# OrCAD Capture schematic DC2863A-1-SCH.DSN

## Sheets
1 PAGE2: size C
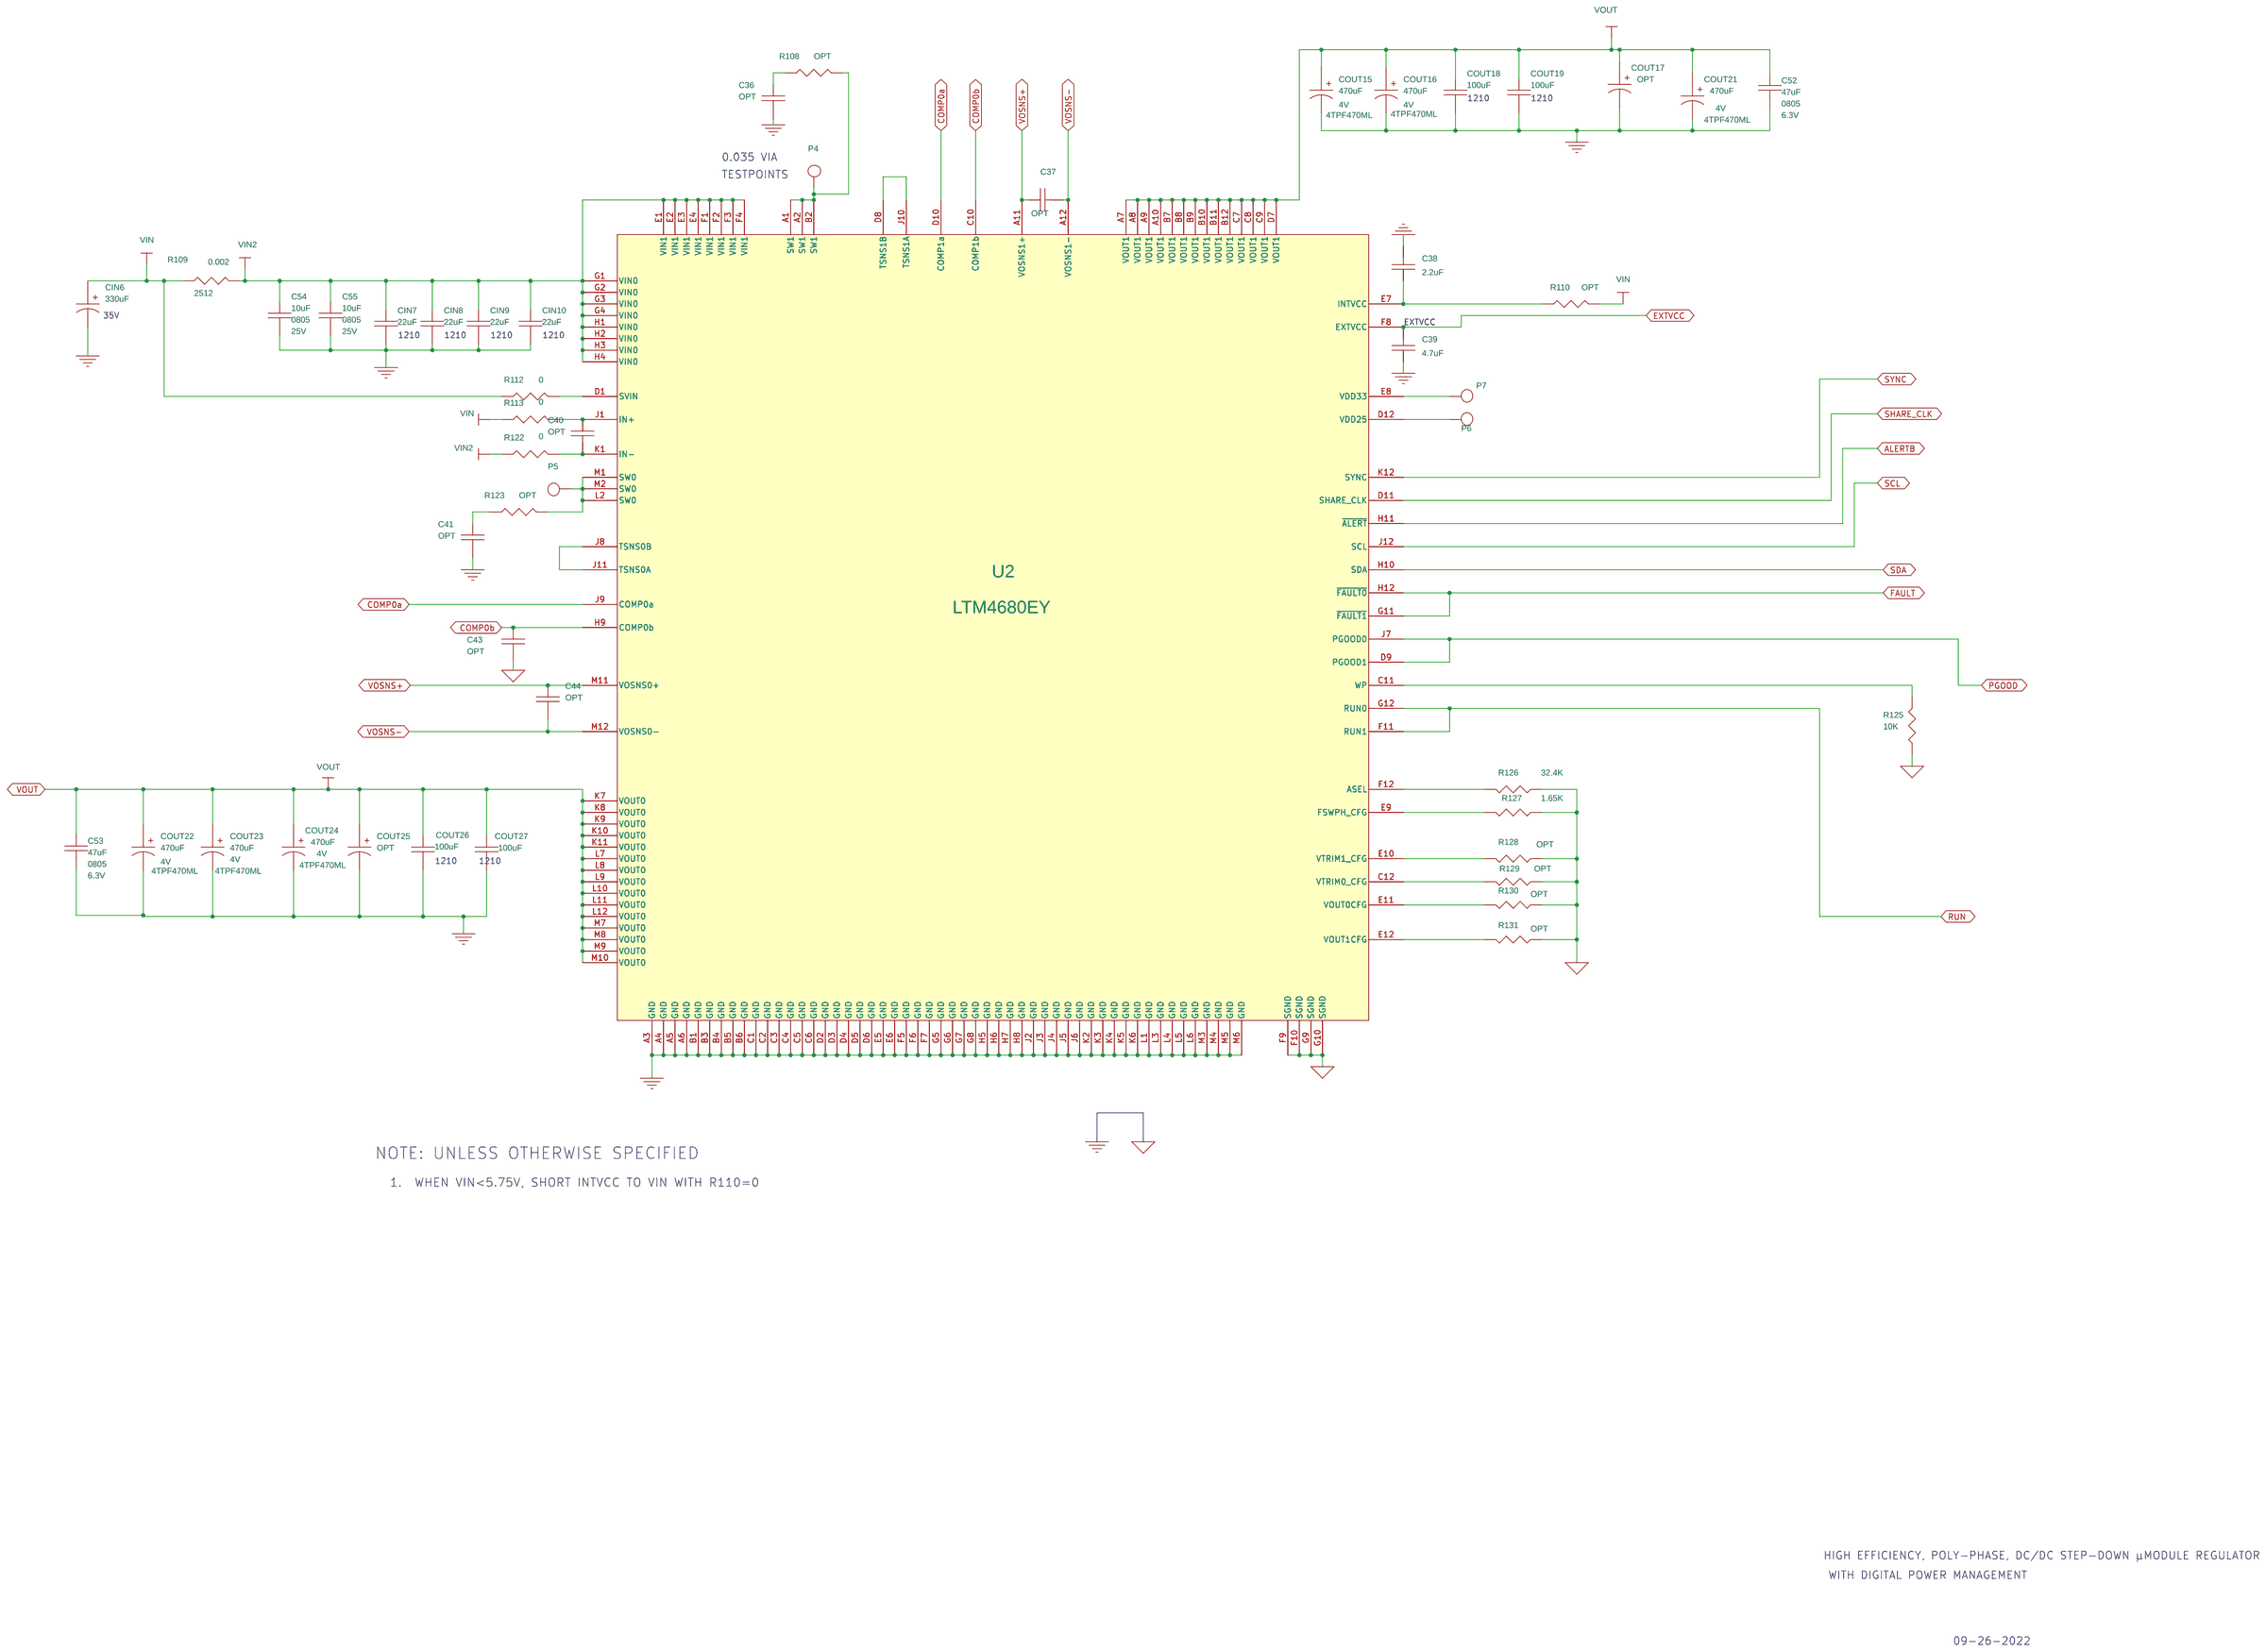
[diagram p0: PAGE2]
2 PAGE4: size B
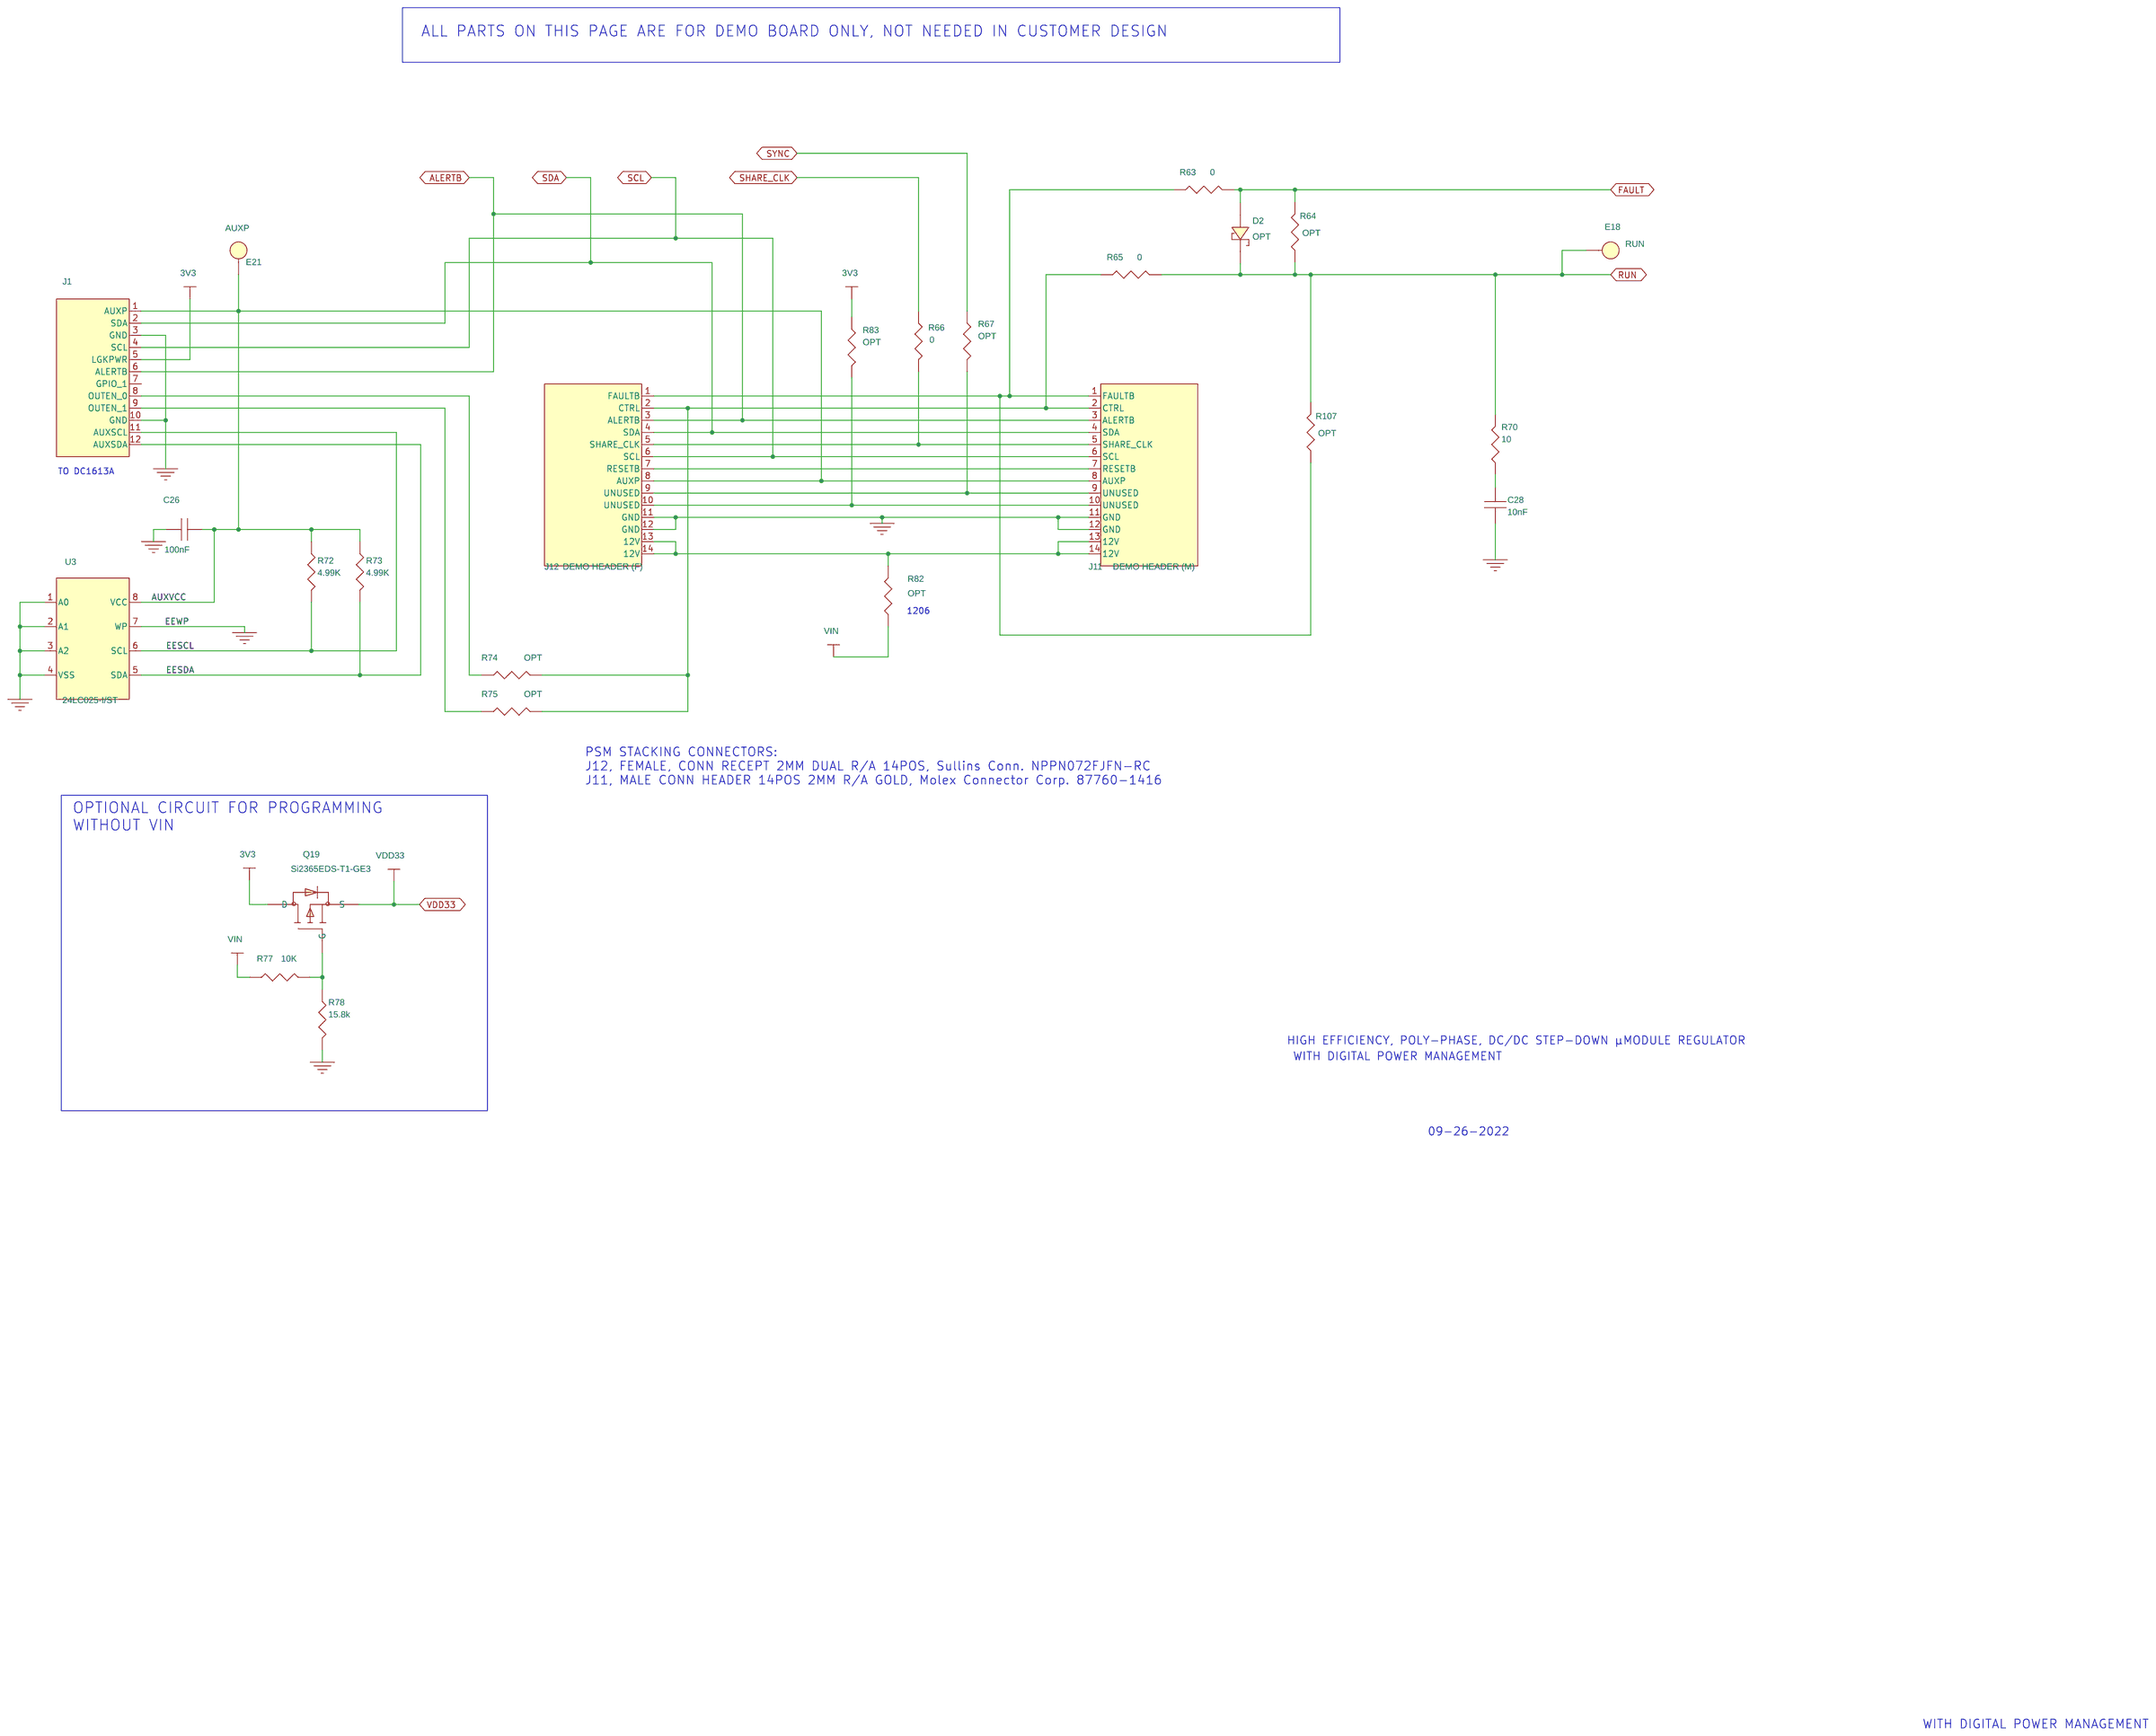
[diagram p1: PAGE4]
3 PAGE1: size C
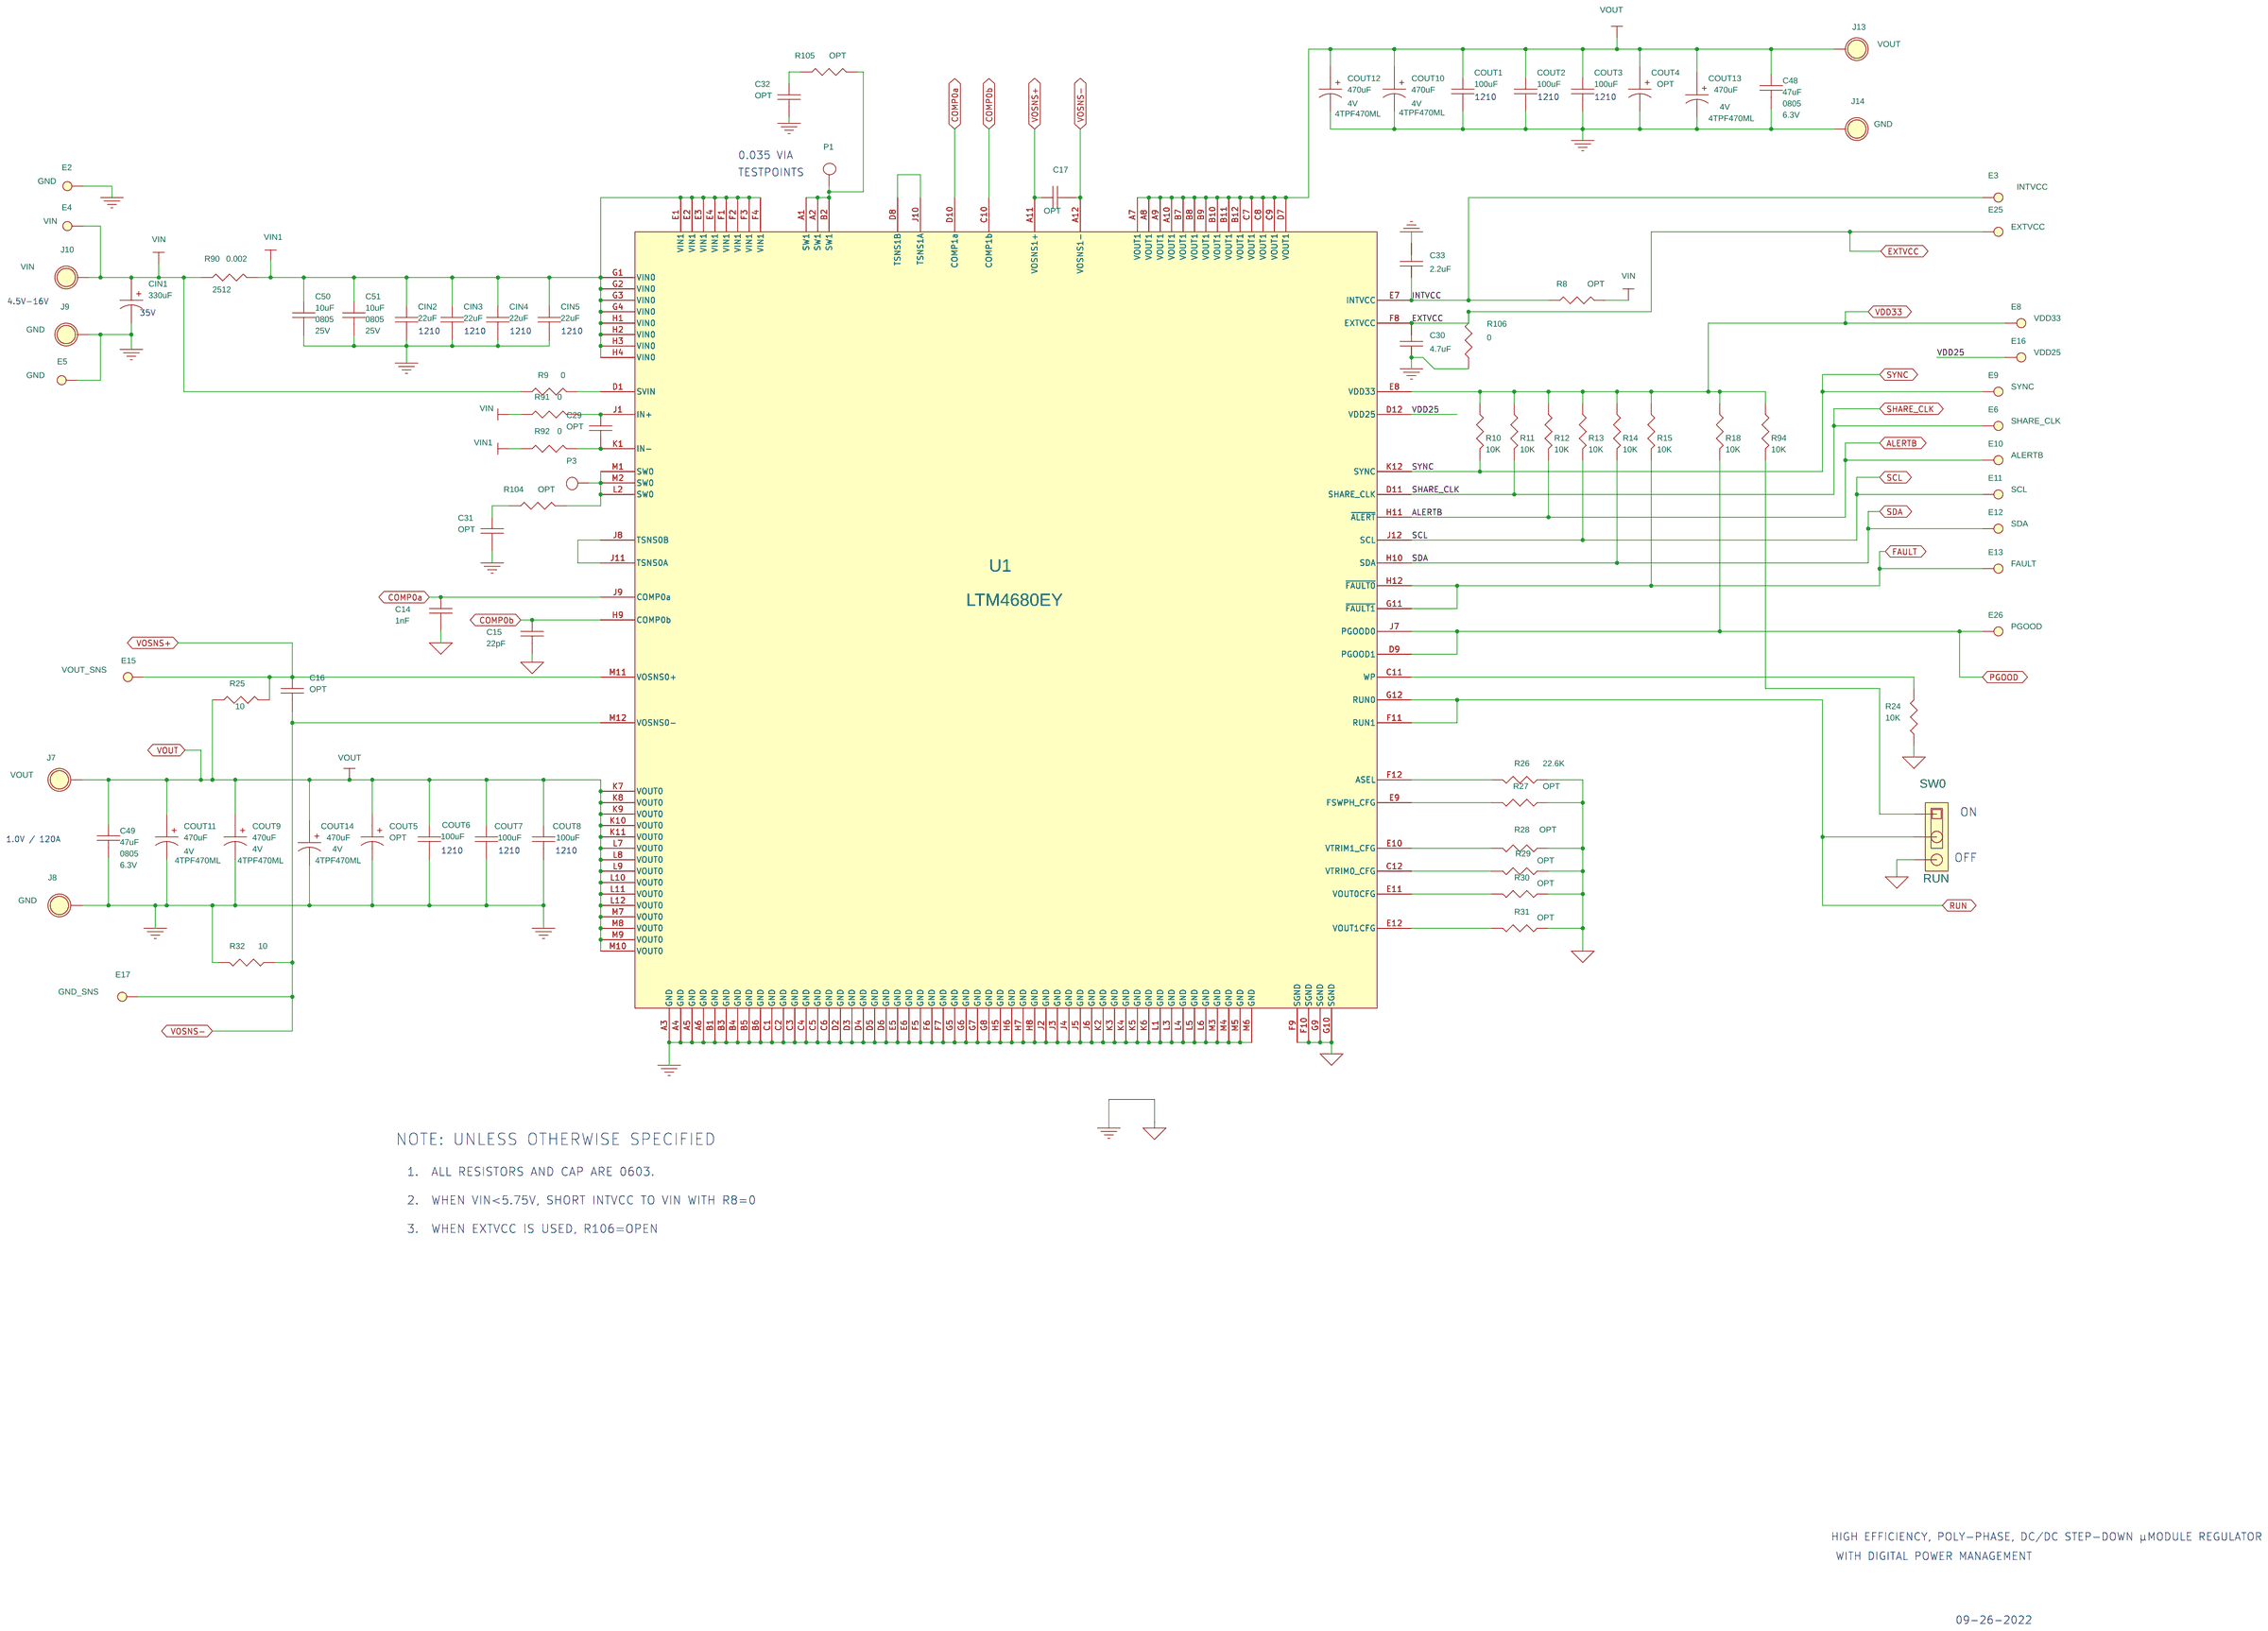
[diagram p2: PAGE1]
4 PAGE3: size Custom
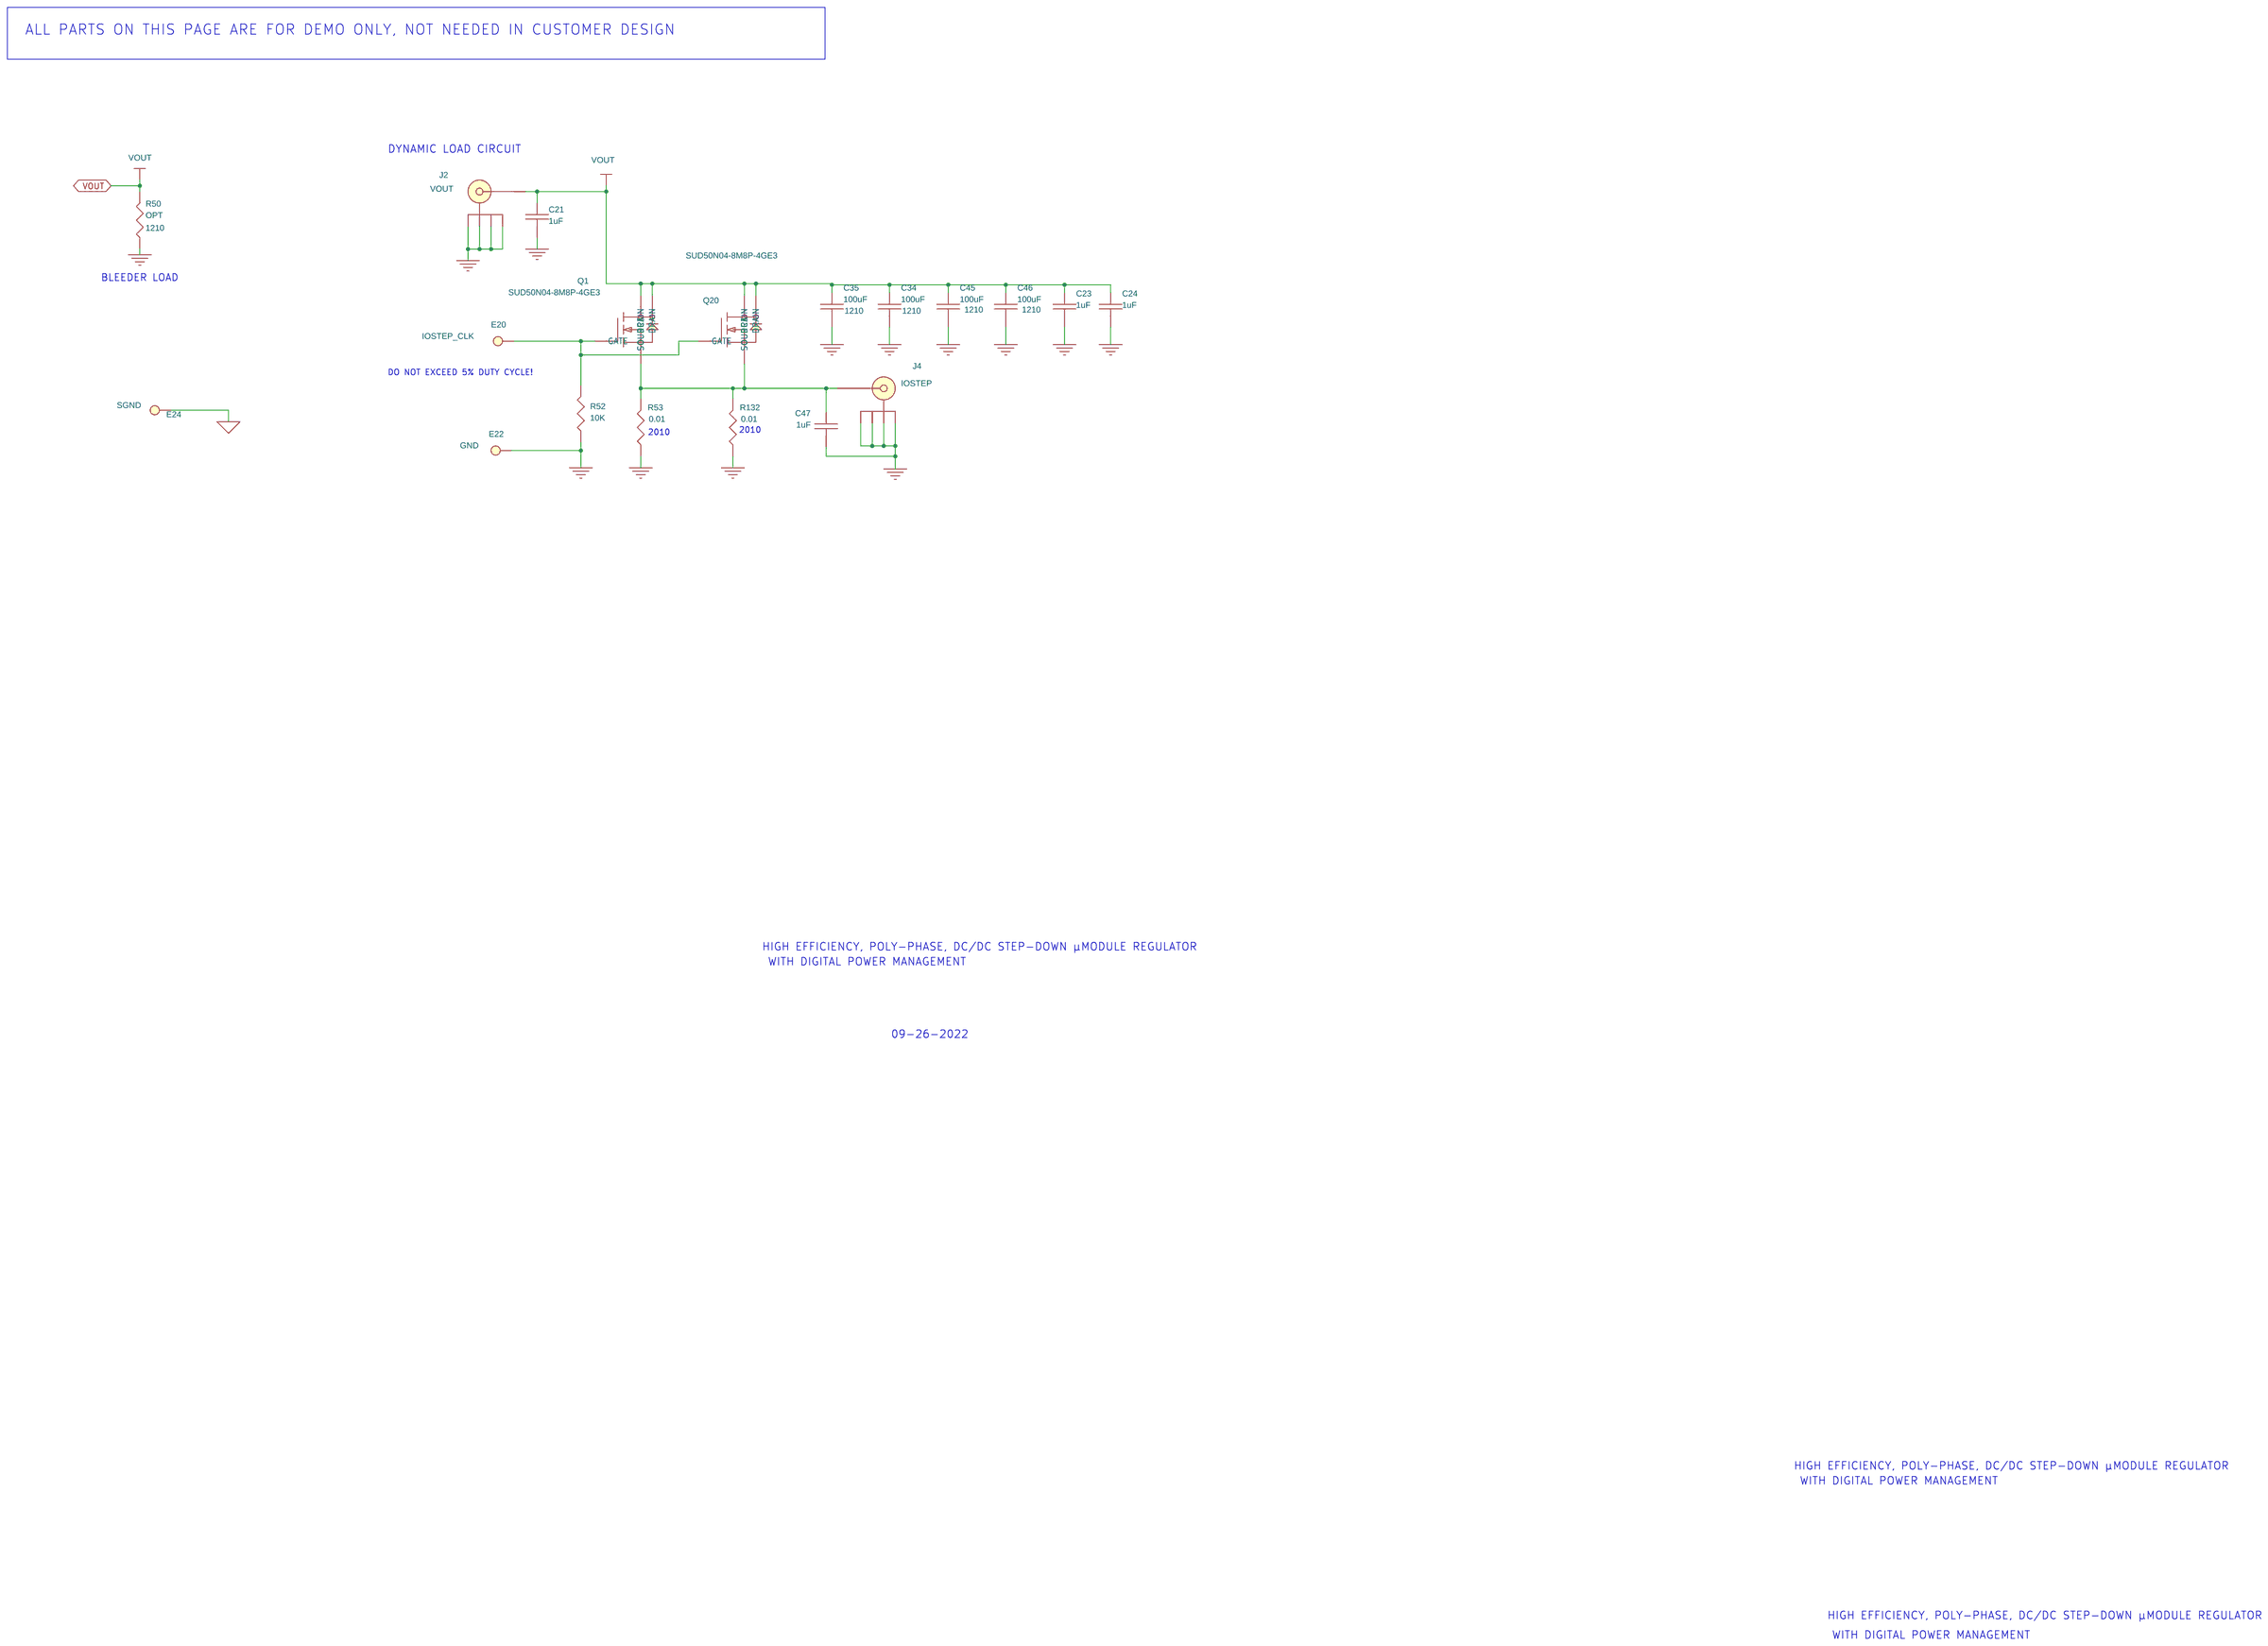
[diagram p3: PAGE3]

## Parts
sheet PAGE1
C14  1nF  [0603]
C15  22pF  [0603]
C16  OPT  [0603]
C17  OPT  [0603]
C29  OPT  [0603]
C30  4.7uF  [0603]
C31  OPT  [0603]
C32  OPT  [0603]
C33  2.2uF  [0603]
C48  47uF  [0805]
C49  47uF  [0805]
C50  10uF  [0805]
C51  10uF  [0805]
CIN1  330uF  [SANYO-F8]
CIN2  22uF  [1210]
CIN3  22uF  [1210]
CIN4  22uF  [1210]
CIN5  22uF  [1210]
COUT1  100uF  [1210]
COUT2  100uF  [1210]
COUT3  100uF  [1210]
COUT4  OPT  [D3L]
COUT5  OPT  [D3L]
COUT6  100uF  [1210]
COUT7  100uF  [1210]
COUT8  100uF  [1210]
COUT9  470uF  [D3L]
COUT10  470uF  [D3L]
COUT11  470uF  [D3L]
COUT12  470uF  [D3L]
COUT13  470uF  [D3L]
COUT14  470uF  [D3L]
E2  GND  [TURRETS]
E3  INTVCC  [TURRETS]
E4  TURRETS  [TURRETS]
E5  GND  [TURRETS]
E6  TURRETS  [TURRETS]
E8  VDD33  [TURRETS]
E9  TURRETS  [TURRETS]
E10  TURRETS  [TURRETS]
E11  TURRETS  [TURRETS]
E12  TURRETS  [TURRETS]
E13  TURRETS  [TURRETS]
E15  TURRETS  [TURRETS]
E16  VDD25  [TURRETS]
E17  TURRETS  [TURRETS]
E25  EXTVCC  [TURRETS]
E26  TURRETS  [TURRETS]
J7  BANANA SMALL  [CON\LUG\10]
J8  BANANA SMALL  [CON\LUG\10]
J9  BANANA SMALL  [CON\LUG\10]
J10  BANANA SMALL  [CON\LUG\10]
J13  BANANA SMALL  [CON\LUG\10]
J14  BANANA SMALL  [CON\LUG\10]
P1  TURRETS  [PAD]
P3  TURRETS  [PAD]
R8  OPT  [0603]
R9  0  [0603]
R10  10K  [0603]
R11  10K  [0603]
R12  10K  [0603]
R13  10K  [0603]
R14  10K  [0603]
R15  10K  [0603]
R18  10K  [0603]
R24  10K  [0603]
R25  10  [0603]
R26  22.6K  [0603]
R27  OPT  [0603]
R28  OPT  [0603]
R29  OPT  [0603]
R30  OPT  [0603]
R31  OPT  [0603]
R32  10  [0603]
R90  0.002  [2512]
R91  0  [0603]
R92  0  [0603]
R94  10K  [0603]
R104  OPT  [0805]
R105  OPT  [0805]
R106  0  [0603]
SW0  3 Pins 2mm Ctrs.  [HD1X3-079]
U1  LTM4680EY  [a]
sheet PAGE2
C36  OPT  [0603]
C37  OPT  [0603]
C38  2.2uF  [0603]
C39  4.7uF  [0603]
C40  OPT  [0603]
C41  OPT  [0603]
C43  OPT  [0603]
C44  OPT  [0603]
C52  47uF  [0805]
C53  47uF  [0805]
C54  10uF  [0805]
C55  10uF  [0805]
CIN6  330uF  [SANYO-F8]
CIN7  22uF  [1210]
CIN8  22uF  [1210]
CIN9  22uF  [1210]
CIN10  22uF  [1210]
COUT15  470uF  [D3L]
COUT16  470uF  [D3L]
COUT17  OPT  [D3L]
COUT18  100uF  [1210]
COUT19  100uF  [1210]
COUT21  470uF  [D3L]
COUT22  470uF  [D3L]
COUT23  470uF  [D3L]
COUT24  470uF  [D3L]
COUT25  OPT  [D3L]
COUT26  100uF  [1210]
COUT27  100uF  [1210]
P4  TURRETS  [PAD]
P5  TURRETS  [PAD]
P6  TURRETS  [PAD]
P7  TURRETS  [PAD]
R108  OPT  [0805]
R109  0.002  [2512]
R110  OPT  [0603]
R112  0  [0603]
R113  0  [0603]
R122  0  [0603]
R123  OPT  [0805]
R125  10K  [0603]
R126  32.4K  [0603]
R127  1.65K  [0603]
R128  OPT  [0603]
R129  OPT  [0603]
R130  OPT  [0603]
R131  OPT  [0603]
U2  LTM4680EY  [a]
sheet PAGE3
C21  1uF  [0603]
C23  1uF  [0805]
C24  1uF  [0603]
C34  100uF  [1210]
C35  100uF  [1210]
C45  100uF  [1210]
C46  100uF  [1210]
C47  1uF  [0603]
E20  IOSTEP_CLK  [TURRETS]
E22  GND  [TURRETS]
E24  SGND  [TURRETS]
J2  VOUT  [BNC]
J4  IOSTEP  [BNC]
Q1  SUD50N04-8M8P-4GE3  [TO252]
Q20  SUD50N04-8M8P-4GE3  [TO252]
R50  OPT  [1210]
R52  10K  [0603]
R53  0.01  [2010]
R132  0.01  [2010]
sheet PAGE4
C26  100nF  [0603]
C28  10nF  [0603]
D2  OPT  [SOD323]
E18  RUN  [TURRETS]
E21  AUXP  [TURRETS]
J1  HD2X6-079  [HD2X6-079-MOLEX]
J11  DEMO HEADER (M)  [NPPN072FJFN]
J12  DEMO HEADER (F)  [NPPN072FJFN-RC]
Q19  Si2365EDS-T1-GE3  [SOT-23]
R63  0  [0603]
R64  OPT  [0603]
R65  0  [0603]
R66  0  [0603]
R67  OPT  [0603]
R70  10  [0603]
R72  4.99K  [0603]
R73  4.99K  [0603]
R74  OPT  [0603]
R75  OPT  [0603]
R77  10K  [0603]
R78  15.8k  [0603]
R82  OPT  [1206]
R83  OPT  [0603]
R107  OPT  [0603]
U3  24LC025-I/ST  [TSSOP-8_4.4MM]

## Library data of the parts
C14-C17 C29-C33 C36-C41 C43 C44 = CAP0603_1: Component: cap; Manufacturer: TDK; Manufacturer P/N: C1608C0G1H102J; Tolerance: 5%; Type: cer 0603; Vendor: Digikey; Vendor P/N: 445-1293-1-ND; Volts/Amps/Watts: 50V
C48 C49 C52 C53 = CAP0603_1: Component: cap; Manufacturer: TDK; Manufacturer P/N: C1608C0G1H102J; Tolerance: 5%; Type: cer 0603; Vendor: Digikey; Vendor P/N: 445-1293-1-ND; Volts/Amps/Watts: 6.3V
C50 C51 C54 C55 = CAP0603_1: Component: cap; Manufacturer: TDK; Manufacturer P/N: C1608C0G1H102J; Tolerance: 5%; Type: cer 0603; Vendor: Digikey; Vendor P/N: 445-1293-1-ND; Volts/Amps/Watts: 25V
CIN1 CIN6 = CAPR12X5_0: Component: cap; Manufacturer: SANYO; Tolerance: 20%; Type: OS-CON; Volts/Amps/Watts: 16V
CIN2-CIN5 CIN7-CIN10 = CAP1210_1: Component: cap; Manufacturer: Taiyo Yuden; Manufacturer P/N: GMK325BJ106KN-T; Tolerance: 10%; Type: cer 1210; Vendor: Digikey; Vendor P/N: 587-1439-1-ND; Volts/Amps/Watts: 35V
C34 C35 C45 C46 COUT1 COUT18 = CAP0603_1: Component: cap; Manufacturer: TDK; Manufacturer P/N: C3225X5R0J107M; Tolerance: 20%; Type: cer 1210 X5R; Vendor: Digikey; Vendor P/N: 445-1437-1-ND; Volts/Amps/Watts: 6.3v
COUT2 COUT3 COUT6-COUT8 COUT19 COUT26 COUT27 = CAP0603_1: Component: cap; Manufacturer: TDK; Manufacturer P/N: C3225X5R0J107M; Part Type: CAP1210; Tolerance: 20%; Type: cer 1210 X5R; Vendor: Digikey; Vendor P/N: 445-1437-1-ND; Volts/Amps/Watts: 6.3v
COUT4 COUT5 COUT17 COUT25 = CAPR12X5_0: Component: cap; Manufacturer: SANYO; Manufacturer P/N: EEFGX0E471R; Tolerance: 20%; Type: SP-CAP; Volts/Amps/Watts: 2.5V
COUT9-COUT16 COUT21-COUT24 = CAPR12X5_0: Component: cap; Manufacturer: SANYO; Manufacturer P/N: 4TPF470ML; Tolerance: 20%; Type: SP-CAP; Volts/Amps/Watts: 4V
E2 E5 E22 = TURRETS_1: Component: tp; Manufacturer: Keystone; Manufacturer P/N: 1593-2; Vendor: Digikey; Vendor P/N: 1593-2K-ND
E3 E8 E16 E20 E24 E25 = TURRETS_1: Component: tp; Label: GND; Manufacturer: Keystone; Manufacturer P/N: 1593-2; Vendor: Digikey; Vendor P/N: 1593-2K-ND
E4 = TURRETS_1: Component: tp; Label: VIN; Manufacturer: Keystone; Manufacturer P/N: 1593-2; Vendor: Digikey; Vendor P/N: 1593-2K-ND
E6 = TURRETS_1: Component: tp; Label: SHARE_CLK; Manufacturer: Keystone; Manufacturer P/N: 1593-2; Vendor: Digikey; Vendor P/N: 1593-2K-ND
E9 = TURRETS_1: Component: tp; Label: SYNC; Manufacturer: Keystone; Manufacturer P/N: 1593-2; Vendor: Digikey; Vendor P/N: 1593-2K-ND
E10 = TURRETS_1: Component: tp; Label: ALERTB; Manufacturer: Keystone; Manufacturer P/N: 1593-2; Vendor: Digikey; Vendor P/N: 1593-2K-ND
E11 = TURRETS_1: Component: tp; Label: SCL; Manufacturer: Keystone; Manufacturer P/N: 1593-2; Vendor: Digikey; Vendor P/N: 1593-2K-ND
E12 = TURRETS_1: Component: tp; Label: SDA; Manufacturer: Keystone; Manufacturer P/N: 1593-2; Vendor: Digikey; Vendor P/N: 1593-2K-ND
E13 = TURRETS_1: Component: tp; Label: FAULT; Manufacturer: Keystone; Manufacturer P/N: 1593-2; Vendor: Digikey; Vendor P/N: 1593-2K-ND
E15 = TURRETS_1: Component: tp; Label: VOUT_SNS; Vendor: Digikey; Vendor P/N: 1593-2K-ND
E17 = TURRETS_1: Component: tp; Label: GND_SNS; Vendor: Digikey; Vendor P/N: 1593-2K-ND
E26 = TURRETS_1: Component: tp; Label: PGOOD; Manufacturer: Keystone; Manufacturer P/N: 1593-2; Vendor: Digikey; Vendor P/N: 1593-2K-ND
J7 J13 = BANANA_SMALL_0: Component: conn; Label: VOUT
J8 J9 J14 = BANANA_SMALL_0: Component: conn; Label: GND
J10 = BANANA_SMALL_0: Component: conn; Label: VIN
P1 P3-P7 = PAD_2: Component: tp; Label: <Label>; Vendor: Digikey; Vendor P/N: 1593-2K-ND
R8 R110 = RES0603_9: Label: OPT 0; Manufacturer: Rohm; Manufacturer P/N: RHM0.0GCT-ND; Vendor: Digikey
R9 R112 = RES0603_3
R10-R15 R18 R24 R29 R30 R91 R92 R94 R104-R106 R108 R113 R122 R123 R125 R129 R130 = RES0603_9: Manufacturer: ROHM; Manufacturer P/N: MCR03EZPFX1002; Vendor: Digikey; Vendor P/N: RHM10.0KHCT-ND; Volts/Amps/Watts: 0.1W
R25 = RES0603_9: Manufacturer: Rohm; Manufacturer P/N: MCR03EZPFX1000; Vendor: Digikey; Vendor P/N: RHM100HCT-ND; Volts/Amps/Watts: 0.1W
R26 R27 R126 R127 = RES0603_9: Manufacturer: Panasonic; Manufacturer P/N: ERJ-3EKF2002V; Vendor: Digikey; Vendor P/N: P20.0KHCT-ND; Volts/Amps/Watts: 0.1W
R28 R128 = RES0603_9: Manufacturer: Panasonic; Manufacturer P/N: ERJ-3EKF1000V; Vendor: Digikey; Vendor P/N: P100HCT-ND; Volts/Amps/Watts: 0.1W
R31 R131 = RES0603_9: Manufacturer: Panasonic; Manufacturer P/N: ERJ-3EKF1021V; Vendor: Digikey; Vendor P/N: P1.02KHCT-ND; Volts/Amps/Watts: 0.1W
R32 = RES0603_9: Manufacturer: Yageo; Manufacturer P/N: RC0603JR-070RL; Tolerance: 5%; Vendor: Digikey; Vendor P/N: 311-0.0GRCT-ND; Volts/Amps/Watts: 0.1W
R90 R109 = RES2512_0: Tolerance: <Tolerance>
SW0 = Commcon2802s03g2_7: 11th Part Field: OFF; 12th Part Field: RUN; 9th Part Field: ON
U1 U2 = LTC3880-M0001_45: Component: IC; Manufacturer: LTC; Manufacturer P/N: LTC3880_M0001; Vendor: LTC; Vendor P/N: LTC3880_M0001
C21 C24 = CAP0603_1
C23 C47 = CAP1206_1: Manufacturer: Kemet; Manufacturer P/N: C1206C106K8RACTU; Tolerance: 10%; Type: cer 1206 X7R; Vendor: Digikey; Vendor P/N: 399-4937-1-ND; Volts/Amps/Watts: 10V
J2 J4 = BNC5-SCH_0
Q1 Q20 = IRF540_0
R50 = RES0603_5: Label: 1W; Manufacturer: VISHAY; Manufacturer P/N: CRCW251230R0JNEG; Tolerance: 5%; Vendor: Digikey; Vendor P/N: 541-30XCT-ND; Volts/Amps/Watts: 0.1W
R52 = RES0603_9
R53 R132 = RES0603_5: Label: 1W; Manufacturer: VISHAY; Manufacturer P/N: CRCW251230R0JNEG; Part Type: 2512; Tolerance: 5%; Vendor: Digikey; Vendor P/N: 541-30XCT-ND; Volts/Amps/Watts: 0.1W
C26 = CAP_NP: CAP, 0603 100nF 20% 16V X7R; Part Number: AVX 0603YC104MAT2A
C28 = CAP_NP: CAP, 0603 10nF 10% 25V X7R; Part Number: AVX 06033C103KAT2A
D2 = DIODE_SCHOTTKY_9: DIODE, SCHOTTKY 30V, 100mA; Part Number: CENTRAL SEMI CMDSH-3-TR
E18 E21 = E_0: TURRET; Part Number: MILL MAX 2501-2-00-80-00-00-07-0
J1 = HD2X6-079-PMBUS_2: HEADER, 12PIN 2mm STR DL; Label: DC1427A HEADER; Manufacturer: MOLEX; Manufacturer P/N: 87831-1220; Part Number: FCI 98414-G06-12ULF; Type: header 12POS 2MM VERT; Vendor: Digikey; Vendor P/N: WM18561-ND
J11 = PMBUS_CONNECTOR20_3: CONN, SOCKET 20PIN  DUAL ROW R/A; Component: con; Manufacturer: Mill Max; Manufacturer P/N: 803-93-020-20-001; Part Number: MILL MAX 803-93-020-20-001; Type: conn  RA 20 dual row; Vendor: LTC; Vendor P/N: 803-93-020-20-001
J12 = PMBUS_HEADER20_3: HEADER, 20PIN DUAL ROW R/A; Component: con; Manufacturer: Mill Max; Manufacturer P/N: 802-40-020-20-0001; Part Number: MILL MAX 802-40-020-20-0001; Type: header RA 20 dual row; Vendor: LTC; Vendor P/N: 802-40-020-20-001
Q19 = P-MOSFET: XSTR, N-CHANNEL DMOS FET; Part Number: VISHAY TP0101K-T1-E3
R63 R65 = RES0603_0: RES, 0603 0 OHMS JUMPER; Label: OPT 0; Manufacturer: Rohm; Manufacturer P/N: RHM0.0GCT-ND; Part Number: VISHAY CRCW06030000Z0EA; Tolerance: 5%; Vendor: Digikey; Vendor P/N: RHM0.0GCT-ND; Volts/Amps/Watts: 0.1W
R64 R67 R75 R83 R107 = RES0603_0: RES, 0603 OPTION; Label: OPT 0; Manufacturer: Rohm; Manufacturer P/N: RHM0.0GCT-ND; Part Number: OPTION; Tolerance: 5%; Vendor: Digikey; Vendor P/N: RHM0.0GCT-ND; Volts/Amps/Watts: 0.1W
R66 = RES0603_0: RES, 0603 0 OHMS JUMPER; Manufacturer: Rohm; Manufacturer P/N: RHM0.0GCT-ND; Part Number: VISHAY CRCW06030000Z0EA; Tolerance: 5%; Vendor: Digikey; Vendor P/N: RHM0.0GCT-ND; Volts/Amps/Watts: 0.1W
R70 = RES0603_1: RES, 0603 10 OHMS 5% 1/10W; Manufacturer: Rohm; Manufacturer P/N: RHM0.0GCT-ND; Part Number: VISHAY CRCW060310R0JNEA; Tolerance: 5%; Vendor: Digikey; Vendor P/N: RHM0.0GCT-ND; Volts/Amps/Watts: 0.1W
R72 R73 = RES0603_0: RES, 0603 4.99K OHMS 1% 1/10W; Manufacturer: ROHM; Manufacturer P/N: MCR03EZPFX4991; Part Number: VISHAY CRCW06034K99FKEA; Vendor: Digikey; Vendor P/N: RHM4.99KHCT-ND; Volts/Amps/Watts: 0.1w
R74 R82 = RES0603_3: RES, 0603 OPTION; Label: OPT 0; Manufacturer: Rohm; Manufacturer P/N: RHM0.0GCT-ND; Part Number: OPTION; Tolerance: 5%; Vendor: Digikey; Vendor P/N: RHM0.0GCT-ND; Volts/Amps/Watts: 0.1W
R77 = RES0603_11: RES, 0603 10K OHMS 5% 1/10W; Part Number: VISHAY CRCW060310K0JNEA
R78 = RES0603_11: RES, 0603 15.8K OHMS 1% 1/10W; Part Number: VISHAY CRCW060315K8FKEA
U3 = 24LC025-I_SN: IC, 24LC05-I/ST; Part Number: MICROCHIP 24LC025-I/ST

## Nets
3V3: J1.5(LGKPWR) Q19.3(D) R83.1
GND_POWER: C21.2 C23.2 C24.2 C26.2 C28.2 C30.1 C31.2 C32.2 C33.2 C34.2 C35.2 C36.2 C38.2 C39.1 C41.2 C45.2 C46.2 C47.2 C48.2 C49.2 C50.2 C51.2 C52.2 C53.2 C54.2 C55.2 CIN1.2 CIN2.2 CIN3.2 CIN4.2 CIN5.2 CIN6.2 CIN7.2 CIN8.2 CIN9.2 CIN10.2 COUT1.2 COUT2.2 COUT3.2 COUT4.2 COUT5.2 COUT6.2 COUT7.2 COUT8.2 COUT9.2 COUT10.2 COUT11.2 COUT12.2 COUT13.2 COUT14.2 COUT15.2 COUT16.2 COUT17.2 COUT18.2 COUT19.2 COUT21.2 COUT22.2 COUT23.2 COUT24.2 COUT25.2 COUT26.2 COUT27.2 E2.1(TP) E5.1(TP) E22.1(TP) J1.3(GND) J1.10(GND) J2.2 J2.3 J2.4 J2.5 J4.2 J4.3 J4.4 J4.5 J8.1(TP) J9.1(TP) J11.11(GND) J11.12(GND) J12.11(GND) J12.12(GND) J14.1(TP) R32.2 R50.1 R52.2 R53.1 R78.2 R106.1 R132.1 U1.A3(GND) U1.A4(GND) U1.A5(GND) U1.A6(GND) U1.B1(GND) U1.B3(GND) U1.B4(GND) U1.B5(GND) U1.B6(GND) U1.C1(GND) U1.C2(GND) U1.C3(GND) U1.C4(GND) U1.C5(GND) U1.C6(GND) U1.D2(GND) U1.D3(GND) U1.D4(GND) U1.D5(GND) U1.D6(GND) U1.E5(GND) U1.E6(GND) U1.F5(GND) U1.F6(GND) U1.F7(GND) U1.G5(GND) U1.G6(GND) U1.G7(GND) U1.G8(GND) U1.H5(GND) U1.H6(GND) U1.H7(GND) U1.H8(GND) U1.J2(GND) U1.J3(GND) U1.J4(GND) U1.J5(GND) U1.J6(GND) U1.K2(GND) U1.K3(GND) U1.K4(GND) U1.K5(GND) U1.K6(GND) U1.L1(GND) U1.L3(GND) U1.L4(GND) U1.L5(GND) U1.L6(GND) U1.M3(GND) U1.M4(GND) U1.M5(GND) U1.M6(GND) U2.A3(GND) U2.A4(GND) U2.A5(GND) U2.A6(GND) U2.B1(GND) U2.B3(GND) U2.B4(GND) U2.B5(GND) U2.B6(GND) U2.C1(GND) U2.C2(GND) U2.C3(GND) U2.C4(GND) U2.C5(GND) U2.C6(GND) U2.D2(GND) U2.D3(GND) U2.D4(GND) U2.D5(GND) U2.D6(GND) U2.E5(GND) U2.E6(GND) U2.F5(GND) U2.F6(GND) U2.F7(GND) U2.G5(GND) U2.G6(GND) U2.G7(GND) U2.G8(GND) U2.H5(GND) U2.H6(GND) U2.H7(GND) U2.H8(GND) U2.J2(GND) U2.J3(GND) U2.J4(GND) U2.J5(GND) U2.J6(GND) U2.K2(GND) U2.K3(GND) U2.K4(GND) U2.K5(GND) U2.K6(GND) U2.L1(GND) U2.L3(GND) U2.L4(GND) U2.L5(GND) U2.L6(GND) U2.M3(GND) U2.M4(GND) U2.M5(GND) U2.M6(GND) U3.1(A0) U3.2(A1) U3.3(A2) U3.4(VSS) U3.7(WP)
GND_SIGNAL: C14.2 C15.2 C43.2 E24.1(TP) R24.1 R26.1 R27.1 R28.1 R29.1 R30.1 R31.1 R125.1 R126.1 R127.1 R128.1 R129.1 R130.1 R131.1 SW0.3 U1.F9(SGND) U1.F10(SGND) U1.G9(SGND) U1.G10(SGND) U2.F9(SGND) U2.F10(SGND) U2.G9(SGND) U2.G10(SGND)
VDD25: E16.1(TP) U1.D12(VDD25)
VDD33: E8.1(TP) Q19.2(S) R10.1 R11.1 R12.1 R13.1 R14.1 R15.1 R18.1 R94.1 U1.E8(VDD33)
VIN: CIN1.1 CIN6.1 E4.1(TP) J10.1(TP) R8.1 R9.1 R77.1 R82.1 R90.1 R91.1 R109.1 R110.1 R112.1 R113.1
VIN1: C50.1 C51.1 CIN2.1 CIN3.1 CIN4.1 CIN5.1 R90.2 R92.1 U1.E1(VIN1) U1.E2(VIN1) U1.E3(VIN1) U1.E4(VIN1) U1.F1(VIN1) U1.F2(VIN1) U1.F3(VIN1) U1.F4(VIN1) U1.G1(VIN0) U1.G2(VIN0) U1.G3(VIN0) U1.G4(VIN0) U1.H1(VIN0) U1.H2(VIN0) U1.H3(VIN0) U1.H4(VIN0)
VIN2: C54.1 C55.1 CIN7.1 CIN8.1 CIN9.1 CIN10.1 R109.2 R122.1 U2.E1(VIN1) U2.E2(VIN1) U2.E3(VIN1) U2.E4(VIN1) U2.F1(VIN1) U2.F2(VIN1) U2.F3(VIN1) U2.F4(VIN1) U2.G1(VIN0) U2.G2(VIN0) U2.G3(VIN0) U2.G4(VIN0) U2.H1(VIN0) U2.H2(VIN0) U2.H3(VIN0) U2.H4(VIN0)
ALERTB: E10.1(TP) J1.6(ALERTB) J11.3(ALERTB) J12.3(ALERTB) R12.2 U1.H11(~{ALERT}) U2.H11(~{ALERT})
AUXVCC: C26.1 E21.1(A) J1.1(AUXP) J11.8(AUXP) J12.8(AUXP) R72.1 R73.1 U3.8(VCC)
COMP0a: C14.1 U1.D10(COMP1a) U1.J9(COMP0a) U2.D10(COMP1a) U2.J9(COMP0a)
COMP0b: C15.1 C43.1 U1.C10(COMP1b) U1.H9(COMP0b) U2.C10(COMP1b) U2.H9(COMP0b)
EESCL: J1.11(AUXSCL) R72.2 U3.6(SCL)
EESDA: J1.12(AUXSDA) R73.2 U3.5(SDA)
EXTVCC: C30.2 C39.2 E25.1(TP) R106.2 U1.F8(EXTVCC) U2.F8(EXTVCC)
FAULT: D2.2(ANODE) E13.1(TP) R15.2 R63.2 R64.2 U1.G11(~{FAULT1}) U1.H12(~{FAULT0}) U2.G11(~{FAULT1}) U2.H12(~{FAULT0})
INTVCC: C33.1 E3.1(TP) R8.2 U1.E7(INTVCC)
PGOOD: E26.1(TP) R18.2 U1.D9(PGOOD1) U1.J7(PGOOD0) U2.D9(PGOOD1) U2.J7(PGOOD0)
RUN: D2.1(CATHODE) E18.1(A) R64.1 R65.2 R70.2 R107.2 SW0.2 U1.F11(RUN1) U1.G12(RUN0) U2.F11(RUN1) U2.G12(RUN0)
SCL: E11.1(TP) J1.4(SCL) J11.6(SCL) J12.6(SCL) R13.2 U1.J12(SCL) U2.J12(SCL)
SDA: E12.1(TP) J1.2(SDA) J11.4(SDA) J12.4(SDA) R14.2 U1.H10(SDA) U2.H10(SDA)
SHARE_CLK: E6.1(TP) R11.2 R66.1 U1.D11(SHARE_CLK) U2.D11(SHARE_CLK)
SYNC: E9.1(TP) R10.2 R67.1 U1.K12(SYNC) U2.K12(SYNC)
VOSNS+: C16.1 C17.1 C37.1 C44.1 E15.1(TP) R25.1 U1.A11(VOSNS1+) U1.M11(VOSNS0+) U2.A11(VOSNS1+) U2.M11(VOSNS0+)
VOSNS-: C16.2 C17.2 C37.2 C44.2 E17.1(TP) R32.1 U1.A12(VOSNS1-) U1.M12(VOSNS0-) U2.A12(VOSNS1-) U2.M12(VOSNS0-)
VOUT: C21.1 C23.1 C24.1 C34.1 C35.1 C45.1 C46.1 C48.1 C49.1 C52.1 C53.1 COUT1.1 COUT2.1 COUT3.1 COUT4.1 COUT5.1 COUT6.1 COUT7.1 COUT8.1 COUT9.1 COUT10.1 COUT11.1 COUT12.1 COUT13.1 COUT14.1 COUT15.1 COUT16.1 COUT17.1 COUT18.1 COUT19.1 COUT21.1 COUT22.1 COUT23.1 COUT24.1 COUT25.1 COUT26.1 COUT27.1 J2.1 J7.1(TP) J13.1(TP) Q1.2(DRAIN) Q1.4(DRAIN) Q20.2(DRAIN) Q20.4(DRAIN) R25.2 R50.2 U1.A7(VOUT1) U1.A8(VOUT1) U1.A9(VOUT1) U1.A10(VOUT1) U1.B7(VOUT1) U1.B8(VOUT1) U1.B9(VOUT1) U1.B10(VOUT1) U1.B11(VOUT1) U1.B12(VOUT1) U1.C7(VOUT1) U1.C8(VOUT1) U1.C9(VOUT1) U1.D7(VOUT1) U1.K7(VOUT0) U1.K8(VOUT0) U1.K9(VOUT0) U1.K10(VOUT0) U1.K11(VOUT0) U1.L7(VOUT0) U1.L8(VOUT0) U1.L9(VOUT0) U1.L10(VOUT0) U1.L11(VOUT0) U1.L12(VOUT0) U1.M7(VOUT0) U1.M8(VOUT0) U1.M9(VOUT0) U1.M10(VOUT0) U2.A7(VOUT1) U2.A8(VOUT1) U2.A9(VOUT1) U2.A10(VOUT1) U2.B7(VOUT1) U2.B8(VOUT1) U2.B9(VOUT1) U2.B10(VOUT1) U2.B11(VOUT1) U2.B12(VOUT1) U2.C7(VOUT1) U2.C8(VOUT1) U2.C9(VOUT1) U2.D7(VOUT1) U2.K7(VOUT0) U2.K8(VOUT0) U2.K9(VOUT0) U2.K10(VOUT0) U2.K11(VOUT0) U2.L7(VOUT0) U2.L8(VOUT0) U2.L9(VOUT0) U2.L10(VOUT0) U2.L11(VOUT0) U2.L12(VOUT0) U2.M7(VOUT0) U2.M8(VOUT0) U2.M9(VOUT0) U2.M10(VOUT0)
N16779036: E20.1(TP) Q1.1(GATE) Q20.1(GATE) R52.1
N16813387: C47.1 J4.1 Q1.3(SOURCE) Q20.3(SOURCE) R53.2 R132.2
N16992964: R9.2 U1.D1(SVIN)
N17166430: P1.1(TP) R105.2 U1.A1(SW1) U1.A2(SW1) U1.B2(SW1)
N17222714: R26.2 U1.F12(ASEL)
N17223298: R27.2 U1.E9(FSWPH_CFG)
N17223884: R28.2 U1.E10(VTRIM1_CFG)
N17224472: R29.2 U1.C12(VTRIM0_CFG)
N17225062: R30.2 U1.E11(VOUT0CFG)
N17225654: R31.2 U1.E12(VOUT1CFG)
N18333697: J11.1(FAULTB) J12.1(FAULTB) R63.1 R107.1
N18333715: J1.8(OUTEN_0) R74.1
N18333717: J1.9(OUTEN_1) R75.1
N18333729: J11.2(CTRL) J12.2(CTRL) R65.1 R74.2 R75.2
N18333793: C28.1 R70.1
N18333815: Q19.1(G) R77.2 R78.1
N18333849: J11.5(SHARE_CLK) J12.5(SHARE_CLK) R66.2
N18333851: J11.7(RESETB) J12.7(RESETB)
N18333853: J11.9(UNUSED) J12.9(UNUSED) R67.2
N18333865: J11.13(12V) J11.14(12V) J12.13(12V) J12.14(12V) R82.2
N18333941: J11.10(UNUSED) J12.10(UNUSED) R83.2
N18377351: U1.D8(TSNS1B) U1.J10(TSNS1A)
N18377392: U1.J8(TSNS0B) U1.J11(TSNS0A)
N18437001: P3.1(TP) R104.2 U1.L2(SW0) U1.M1(SW0) U1.M2(SW0)
N18440006: C29.1 R91.2 U1.J1(IN+)
N18440037: C29.2 R92.2 U1.K1(IN-)
N18449385: R24.2 U1.C11(WP)
N18450678: R94.2 SW0.1
N18468612: C31.1 R104.1
N18469531: C32.1 R105.1
N18538301: C36.1 R108.1
N18538305: P4.1(TP) R108.2 U2.A1(SW1) U2.A2(SW1) U2.B2(SW1)
N18538461: U2.D8(TSNS1B) U2.J10(TSNS1A)
N18538808: C38.1 R110.2 U2.E7(INTVCC)
N18539014: R112.2 U2.D1(SVIN)
N18539016: P7.1(TP) U2.E8(VDD33)
N18539076: C40.1 R113.2 U2.J1(IN+)
N18539078: P6.1(TP) U2.D12(VDD25)
N18539185: C40.2 R122.2 U2.K1(IN-)
N18539224: P5.1(TP) R123.2 U2.L2(SW0) U2.M1(SW0) U2.M2(SW0)
N18539268: C41.1 R123.1
N18539301: U2.J8(TSNS0B) U2.J11(TSNS0A)
N18539435: R125.2 U2.C11(WP)
N18539556: R126.2 U2.F12(ASEL)
N18539574: R127.2 U2.E9(FSWPH_CFG)
N18539687: R128.2 U2.E10(VTRIM1_CFG)
N18539726: R129.2 U2.C12(VTRIM0_CFG)
N18539753: R130.2 U2.E11(VOUT0CFG)
N18539807: R131.2 U2.E12(VOUT1CFG)

Not connected (* = marked no-connect by the designer): J1 7(GPIO_1)

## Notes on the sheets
sheet 1
- 1210
- 1210
- 0.035 VIA
- TESTPOINTS
- 35V
- 1210
- 1210
- 1210
- 1210
- 1210
- 1210
- NOTE: UNLESS OTHERWISE SPECIFIED
- 1.  WHEN VIN<5.75V, SHORT INTVCC TO VIN WITH R110=0
- HIGH EFFICIENCY, POLY-PHASE, DC/DC STEP-DOWN µMODULE REGULATOR
- WITH DIGITAL POWER MANAGEMENT
- 09-26-2022
sheet 2
- ALL PARTS ON THIS PAGE ARE FOR DEMO BOARD ONLY, NOT NEEDED IN CUSTOMER DESIGN
- TO DC1613A
- 1206
- PSM STACKING CONNECTORS:
  J12, FEMALE, CONN RECEPT 2MM DUAL R/A 14POS, Sullins Conn. NPPN072FJFN-RC
  J11, MALE CONN HEADER 14POS 2MM R/A GOLD, Molex Connector Corp. 87760-1416
- OPTIONAL CIRCUIT FOR PROGRAMMING
  WITHOUT VIN
- HIGH EFFICIENCY, POLY-PHASE, DC/DC STEP-DOWN µMODULE REGULATOR
- WITH DIGITAL POWER MANAGEMENT
- 09-26-2022
- WITH DIGITAL POWER MANAGEMENT
sheet 3
- 1210
- 1210
- 1210
- 0.035 VIA
- TESTPOINTS
- 4.5V-16V
- 35V
- 1210
- 1210
- 1210
- 1210
- ON
- 1.0V / 120A
- 1210
- 1210
- 1210
- OFF
- NOTE: UNLESS OTHERWISE SPECIFIED
- 1.  ALL RESISTORS AND CAP ARE 0603.
- 2.  WHEN VIN<5.75V, SHORT INTVCC TO VIN WITH R8=0
- 3.  WHEN EXTVCC IS USED, R106=OPEN
- HIGH EFFICIENCY, POLY-PHASE, DC/DC STEP-DOWN µMODULE REGULATOR
- WITH DIGITAL POWER MANAGEMENT
- 09-26-2022
sheet 4
- ALL PARTS ON THIS PAGE ARE FOR DEMO ONLY, NOT NEEDED IN CUSTOMER DESIGN
- DYNAMIC LOAD CIRCUIT
- BLEEDER LOAD
- DO NOT EXCEED 5% DUTY CYCLE!
- 2010
- 2010
- HIGH EFFICIENCY, POLY-PHASE, DC/DC STEP-DOWN µMODULE REGULATOR
- WITH DIGITAL POWER MANAGEMENT
- 09-26-2022
- HIGH EFFICIENCY, POLY-PHASE, DC/DC STEP-DOWN µMODULE REGULATOR
- WITH DIGITAL POWER MANAGEMENT
- HIGH EFFICIENCY, POLY-PHASE, DC/DC STEP-DOWN µMODULE REGULATOR
- WITH DIGITAL POWER MANAGEMENT
